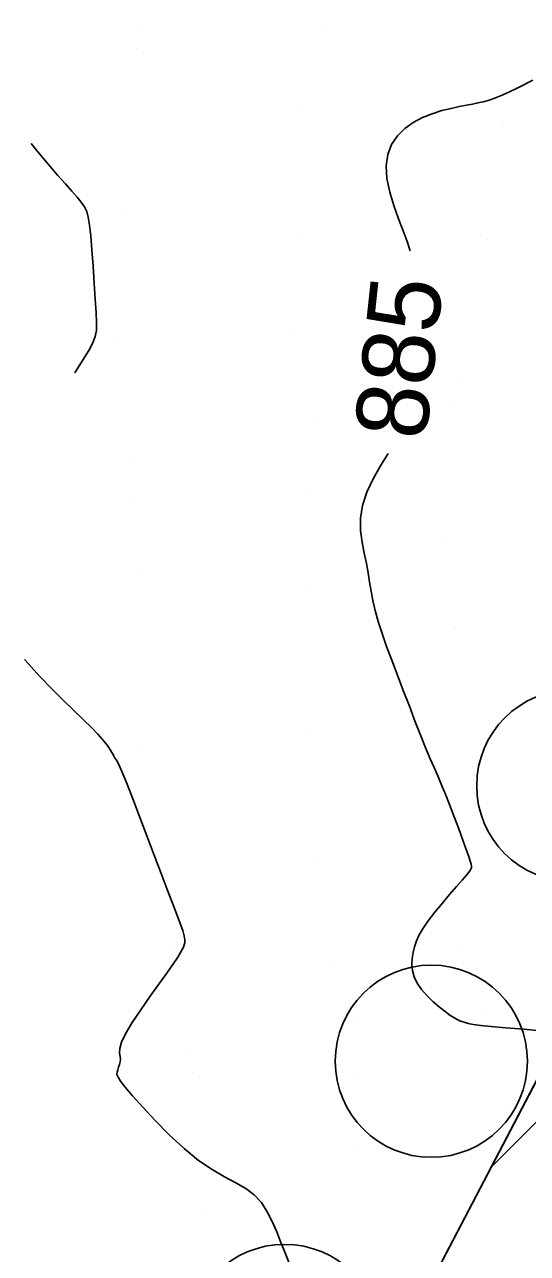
# Model space of a CAD drawing. Extents: x 400243 to 403697, y 4403637 to 4408083.
# Drawn here: x 402557.6 to 402609.9, y 4406077.2 to 4406205.1 of the extents above; entities that cross this region are included whole.
import ezdxf

# ---------------------------------------------------------------- set-up
doc = ezdxf.new("R2010")
doc.units = 0
for name, color, linetype in [('ADAKENARI', 7, 'Continuous'), ('HH_IC', 7, 'Continuous'), ('PL_GES', 7, 'Continuous'), ('SNR_MULKIYET', 7, 'Continuous'), ('SNR_ONAMA', 7, 'Continuous'), ('TR_GES', 7, 'Continuous')]:
    doc.layers.add(name, color=color, linetype=linetype)

msp = doc.modelspace()

# ---------------------------------------------------------------- linework, layer by layer
at = {"layer": 'ADAKENARI'}
msp.add_line((402560.49, 4405998.76), (402635.88, 4406143.05), dxfattribs=at)
at = {"layer": 'HH_IC'}
for p, q in [((402588.48, 4406205.13), (402588.48, 4406205.13)), ((402569.72, 4406204.55), (402569.72, 4406204.55)), ((402569.27, 4406202.69), (402569.27, 4406202.69)), ((402586.55, 4406196.45), (402586.55, 4406196.45)), ((402607.44, 4406194.54), (402607.44, 4406194.54)), ((402567.96, 4406185.97), (402567.96, 4406185.97)), ((402586.09, 4406183.05), (402586.09, 4406183.05)), ((402605.76, 4406182.75), (402605.76, 4406182.75)), ((402567.33, 4406172.67), (402567.33, 4406172.67)), ((402585.42, 4406173.11), (402585.42, 4406173.11)), ((402603.06, 4406168.45), (402603.06, 4406168.45)), ((402601.99, 4406165.79), (402601.99, 4406165.79)), ((402588.08, 4406164.38), (402588.08, 4406164.38)), ((402568.69, 4406160.09), (402568.69, 4406160.09)), ((402587.4, 4406156.19), (402587.4, 4406156.19)), ((402568.78, 4406155.39), (402568.78, 4406155.39)), ((402601.11, 4406151.82), (402601.11, 4406151.82)), ((402569.55, 4406148.32), (402569.55, 4406148.32)), ((402587.42, 4406146.24), (402587.42, 4406146.24)), ((402602.44, 4406142.22), (402602.44, 4406142.22)), ((402586.93, 4406131.15), (402586.93, 4406131.15)), ((402569.87, 4406129.89), (402569.87, 4406129.89)), ((402604.25, 4406127.88), (402604.25, 4406127.88)), ((402588.23, 4406117.79), (402588.23, 4406117.79)), ((402604.03, 4406117.34), (402604.03, 4406117.34)), ((402573.24, 4406109.32), (402573.24, 4406109.32)), ((402602.66, 4406109.22), (402602.66, 4406109.22)), ((402589.52, 4406107.56), (402589.52, 4406107.56)), ((402605.21, 4406102.25), (402605.21, 4406102.25)), ((402592.36, 4406101.13), (402592.36, 4406101.13)), ((402574.91, 4406097.96), (402574.91, 4406097.96)), ((402575.14, 4406096.06), (402575.14, 4406096.06)), ((402591.9, 4406095.62), (402591.9, 4406095.62)), ((402608.08, 4406092.2), (402608.08, 4406092.2)), ((402592.45, 4406088.36), (402592.45, 4406088.36)), ((402576.54, 4406081.61), (402576.54, 4406081.61))]:
    msp.add_line(p, q, dxfattribs=at)
for points in [[(402597.75, 4406181.58), (402597.43, 4406182.56), (402597.01, 4406183.66), (402596.54, 4406184.91), (402596.05, 4406186.28), (402595.62, 4406187.7), (402595.33, 4406189.11), (402595.24, 4406190.43), (402595.41, 4406191.61), (402595.82, 4406192.64), (402596.42, 4406193.54), (402597.18, 4406194.3), (402598.07, 4406194.93), (402599.04, 4406195.44), (402600.04, 4406195.85), (402601.05, 4406196.17), (402602, 4406196.41), (402602.86, 4406196.6), (402603.6, 4406196.74), (402604.23, 4406196.86), (402604.8, 4406196.97), (402605.34, 4406197.09), (402605.88, 4406197.24), (402606.46, 4406197.44), (402607.14, 4406197.71), (402608, 4406198.1), (402609.09, 4406198.63), (402610.5, 4406199.34)], [(402558.3, 4406192.76), (402559, 4406191.9), (402560.1, 4406190.58), (402561.05, 4406189.47), (402561.86, 4406188.55), (402562.54, 4406187.79), (402563.09, 4406187.16), (402563.52, 4406186.63), (402563.84, 4406186.16), (402564.08, 4406185.67), (402564.25, 4406185.07), (402564.38, 4406184.26), (402564.5, 4406183.15), (402564.62, 4406181.69), (402564.75, 4406179.99), (402564.87, 4406178.23), (402564.98, 4406176.55), (402565.06, 4406175.13), (402565.11, 4406174.07), (402565.1, 4406173.29), (402564.98, 4406172.65), (402564.72, 4406172), (402564.29, 4406171.21), (402563.65, 4406170.16), (402562.84, 4406168.87)], [(402611.87, 4406100.34), (402609.62, 4406100.57), (402607.68, 4406100.72), (402606.19, 4406100.85), (402605.1, 4406100.96), (402604.32, 4406101.07), (402603.77, 4406101.17), (402603.35, 4406101.28), (402602.99, 4406101.4), (402602.64, 4406101.56), (402602.28, 4406101.77), (402601.87, 4406102.04), (402601.38, 4406102.4), (402600.79, 4406102.87), (402600.15, 4406103.42), (402599.51, 4406104.03), (402598.93, 4406104.68), (402598.46, 4406105.34), (402598.15, 4406106.01), (402597.98, 4406106.66), (402597.93, 4406107.3), (402597.96, 4406107.93), (402598.06, 4406108.54), (402598.2, 4406109.14), (402598.41, 4406109.75), (402598.7, 4406110.39), (402599.1, 4406111.08), (402599.63, 4406111.86), (402600.3, 4406112.74), (402601.06, 4406113.66), (402601.84, 4406114.57), (402602.56, 4406115.4), (402603.17, 4406116.09), (402603.6, 4406116.59), (402603.88, 4406116.93), (402604.04, 4406117.15), (402604.11, 4406117.29), (402604.13, 4406117.41), (402604.13, 4406117.54), (402604.09, 4406117.73), (402604, 4406118.05), (402603.84, 4406118.54), (402603.59, 4406119.27), (402603.24, 4406120.25), (402602.81, 4406121.42), (402602.34, 4406122.68), (402601.85, 4406123.94), (402601.4, 4406125.09), (402600.99, 4406126.07), (402600.61, 4406126.94), (402600.24, 4406127.79), (402599.83, 4406128.71), (402599.38, 4406129.78), (402598.86, 4406131.09), (402598.27, 4406132.57), (402597.66, 4406134.17), (402597.03, 4406135.81), (402596.42, 4406137.43), (402595.83, 4406138.96), (402595.3, 4406140.4), (402594.82, 4406141.74), (402594.42, 4406142.99), (402594.09, 4406144.13), (402593.86, 4406145.17), (402593.68, 4406146.15), (402593.53, 4406147.09), (402593.38, 4406148.05), (402593.2, 4406149.04), (402592.97, 4406150.11), (402592.75, 4406151.25), (402592.59, 4406152.46), (402592.58, 4406153.74), (402592.78, 4406155.07), (402593.23, 4406156.45), (402593.88, 4406157.84), (402594.65, 4406159.2), (402595.47, 4406160.47)], [(402557.62, 4406139.03), (402557.99, 4406138.61), (402559.2, 4406137.29), (402560.42, 4406136.04), (402561.61, 4406134.86), (402562.72, 4406133.78), (402563.72, 4406132.81), (402564.57, 4406131.97), (402565.24, 4406131.28), (402565.74, 4406130.72), (402566.11, 4406130.26), (402566.37, 4406129.89), (402566.56, 4406129.6), (402566.7, 4406129.36), (402566.82, 4406129.16), (402566.91, 4406128.99), (402566.99, 4406128.84), (402567.08, 4406128.71), (402567.18, 4406128.55), (402567.32, 4406128.31), (402567.53, 4406127.87), (402567.84, 4406127.16), (402568.28, 4406126.07), (402568.87, 4406124.55), (402569.57, 4406122.71), (402570.33, 4406120.7), (402571.1, 4406118.67), (402571.82, 4406116.76), (402572.47, 4406115.09), (402573.01, 4406113.68), (402573.47, 4406112.51), (402573.82, 4406111.57), (402574.07, 4406110.83), (402574.22, 4406110.27), (402574.29, 4406109.87), (402574.29, 4406109.57), (402574.23, 4406109.33), (402574.15, 4406109.11), (402574.03, 4406108.86), (402573.84, 4406108.53), (402573.56, 4406108.07), (402573.12, 4406107.41), (402572.49, 4406106.51), (402571.66, 4406105.35), (402570.69, 4406104), (402569.71, 4406102.59), (402568.82, 4406101.25), (402568.13, 4406100.09), (402567.72, 4406099.2), (402567.53, 4406098.55), (402567.5, 4406098.08), (402567.55, 4406097.73), (402567.59, 4406097.45), (402567.57, 4406097.17), (402567.5, 4406096.89), (402567.4, 4406096.61), (402567.31, 4406096.35), (402567.24, 4406096.1), (402567.23, 4406095.86), (402567.34, 4406095.56), (402567.6, 4406095.14), (402568.09, 4406094.52), (402568.85, 4406093.63), (402569.92, 4406092.44), (402571.22, 4406091.05), (402572.68, 4406089.57), (402574.21, 4406088.15), (402575.71, 4406086.91), (402577.13, 4406085.95), (402578.43, 4406085.2), (402579.6, 4406084.58), (402580.63, 4406083.98), (402581.52, 4406083.32), (402582.26, 4406082.51), (402582.87, 4406081.57), (402583.4, 4406080.55), (402583.86, 4406079.47), (402584.3, 4406078.37), (402584.75, 4406077.28), (402585.16, 4406076.2)]]:
    msp.add_lwpolyline(points, dxfattribs=at)
at = {"layer": 'PL_GES'}
msp.add_lwpolyline([(402649.95, 4406132.25), (402678.87, 4406136.48), (402678.5, 4406122.19), (402698.51, 4406122.19), (402697.33, 4406076.45), (402698.29, 4406075.22), (402609.95, 4405979.43), (402560.49, 4405998.76), (402635.88, 4406143.05)], close=True, dxfattribs=at)
at = {"layer": 'SNR_MULKIYET'}
msp.add_line((402635.88, 4406143.05), (402560.49, 4405998.76), dxfattribs=at)
at = {"layer": 'SNR_ONAMA'}
for centre in [(402614.67, 4406125.9), (402599.95, 4406097.23), (402584.68, 4406068.17)]:
    msp.add_circle(centre, 10, dxfattribs=at)
at = {"layer": 'TR_GES'}
msp.add_line((402606.19, 4406086.22), (402652.61, 4406132.64), dxfattribs=at)

# ---------------------------------------------------------------- texts
at = {"layer": 'HH_IC'}
msp.add_text('885', height=7.5, rotation=83.8521, dxfattribs=at).set_placement((402599.38, 4406161.77))

doc.saveas('drawing.dxf')
